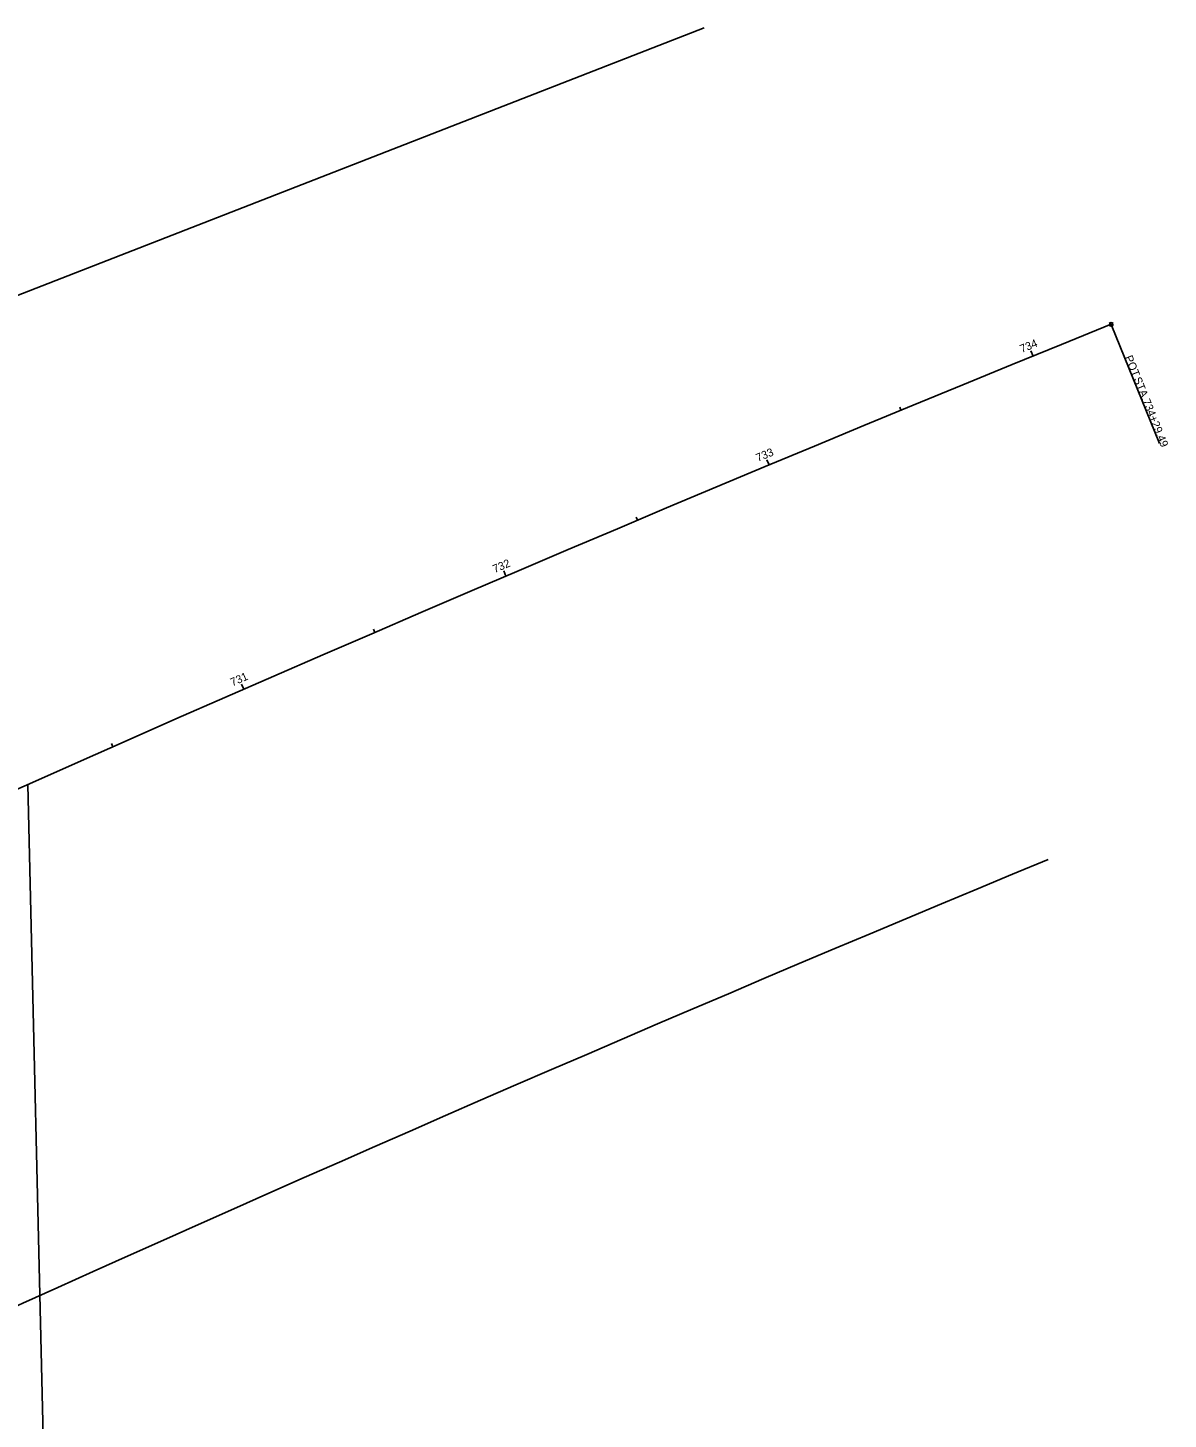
# Model space of a CAD drawing. Extents: x 197895 to 202694, y 454260 to 456995.
# Drawn here: x 201488.7 to 201888, y 456508 to 456995 of the extents above; entities that cross this region are included whole.
import ezdxf

# ---------------------------------------------------------------- set-up
doc = ezdxf.new("R2010")
doc.units = 0
for name, color, linetype in [('DR_X_Ditch', 7, 'Continuous'), ('PM_X_Surveyed_Line', 7, 'Continuous'), ('PV_X_Shoulder_Aggregate', 7, 'Continuous'), ('SV_X_Control_Cells_Found', 7, 'Continuous'), ('SV_X_Shot_Marker', 7, 'Continuous'), ('SV_X_Top_of_Bank', 7, 'Continuous'), ('SV_X_Void_Area', 7, 'Continuous')]:
    doc.layers.add(name, color=color, linetype=linetype)

msp = doc.modelspace()

# ---------------------------------------------------------------- linework, layer by layer
at = {"layer": 'DR_X_Ditch'}
msp.add_line((201868.01, 456891.21), (201884.89, 456849.5), dxfattribs=at)
msp.add_circle((201868.01, 456891.21), 0.6, dxfattribs=at)
at = {"layer": 'PM_X_Surveyed_Line'}
msp.add_arc((206475.15, 445510.73), 12112.67, 112.468785, 116.55179, dxfattribs=at)
at = {"layer": 'PV_X_Shoulder_Aggregate'}
for p, q in [((201840.68, 456880.11), (201839.93, 456881.96)), ((201794.42, 456861.14), (201793.96, 456862.25)), ((201748.24, 456841.99), (201747.47, 456843.83)), ((201702.13, 456822.64), (201701.66, 456823.75)), ((201656.1, 456803.11), (201655.32, 456804.95)), ((201610.16, 456783.39), (201609.68, 456784.49)), ((201564.29, 456763.49), (201563.49, 456765.32)), ((201518.5, 456743.39), (201518.02, 456744.49))]:
    msp.add_line(p, q, dxfattribs=at)
at = {"layer": 'SV_X_Control_Cells_Found'}
msp.add_arc((206475.15, 445510.73), 12277.67, 112.039489, 134.330526, dxfattribs=at)
at = {"layer": 'SV_X_Shot_Marker'}
for p, q in [((201867.34, 456890.54), (201868.67, 456891.88)), ((201867.34, 456891.88), (201868.67, 456890.54))]:
    msp.add_line(p, q, dxfattribs=at)
at = {"layer": 'SV_X_Top_of_Bank'}
msp.add_line((201063.88, 456737.31), (201725.54, 456994.98), dxfattribs=at)
at = {"layer": 'SV_X_Void_Area'}
msp.add_line((201507.5, 455928.55), (201488.71, 456730.2), dxfattribs=at)

# ---------------------------------------------------------------- texts
at = {"layer": 'DR_X_Ditch'}
for s, p in [('POT', (201872.71, 456879.69)), (' STA. ', (201875.39, 456873.08)), ('734+29.49', (201878.88, 456864.44))]:
    msp.add_text(s, height=2.8, rotation=292.0395, dxfattribs=at).set_placement(p)
at = {"layer": 'PV_X_Shoulder_Aggregate'}
for s, rotation, p in [('734', 22.1771, (201836.7, 456881.19)), ('733', 22.6438, (201744.32, 456843.06)), ('732', 23.1105, (201652.17, 456804.15)), ('731', 23.5771, (201560.34, 456764.49))]:
    msp.add_text(s, height=2.8, rotation=rotation, dxfattribs=at).set_placement(p)

doc.saveas('drawing.dxf')
